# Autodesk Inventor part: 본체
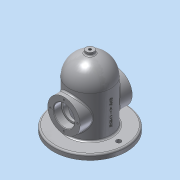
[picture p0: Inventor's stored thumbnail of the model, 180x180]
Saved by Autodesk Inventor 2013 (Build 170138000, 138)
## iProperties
Created: 2019-11
Part Number: 본체
Material: 알루미늄 6061
Document SubType Name: Modeling
Designer: Administrator
Density: 2.71 g/cm^3
Mass: 1111.16 g
Surface Area: 892.162 cm^2
Volume: 410.022 cm^3
Author: Administrator
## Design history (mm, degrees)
sketch "스케치1"
  geometry: C1 r 70 at (0, 0); 1 further point
  constraints: 1 centre point, 1 coincident
  dimensions: "d0" = 140 diameter of C1
extrude "돌출1" new body sketch "스케치1" distance "d1" = 10; taper "d2" = 0 deg
sketch "스케치2"
  geometry: C1 r 70 at (0, 0) reference; C2 r 40 at (0, 0)
  constraints: 1 centre point, 1 coincident
  dimensions: "d3" = 80 diameter of C2
extrude "돌출2" join sketch "스케치2" distance "d4" = 80; taper "d5" = 0 deg
sketch "스케치3"
  geometry: L1 (-70, 0)-(-70, 10) reference; L2 (-70, 10)-(-40, 10) reference; L3 (-40, 10)-(-40, 90) reference; L4 (-40, 90)-(40, 90) reference; L5 (40, 90)-(40, 10) reference; L6 (40, 10)-(70, 10) reference; L7 (70, 10)-(70, 0) reference; L8 (70, 0)-(-70, 0) reference; L9 (0, 130)-(0, 90); L10 (-40, 90)-(0, 90); A1 r 40 centre (0, 90) between (40, 90) and (0, 130); A2 r 40 centre (0, 90) between (0, 130) and (-40, 90); 1 further point
  constraints: 4 end point, 4 point on circle, 4 tangent, 2 centre point, 2 perpendicular
revolve "회전1" sketch "스케치3" stored, may be unused: angle "d6" = 90 deg
sketch "스케치4"
  geometry: L1 (-70, 0)-(-70, 10) reference; L2 (-70, 10)-(-40, 10) reference; L3 (-40, 10)-(-40, 90) reference; L4 (40, 90)-(40, 10) reference; L5 (40, 10)-(70, 10) reference; L6 (70, 10)-(70, 0) reference; L7 (70, 0)-(-70, 0) reference; C1 r 31 at (0, 50); A1 r 40 centre (0, 90) between (40, 90) and (0, 130) reference; A2 r 40 centre (0, 90) between (0, 130) and (-40, 90) reference; 1 further point
  constraints: 1 centre point, 1 vertical alignment
  dimensions: "d7" = 62 diameter of C1; "d8" = 50 distance from line of L7 C1.centre
extrude "돌출3" join sketch "스케치4" stored distance "d9" = 100; taper "d10" = 0 deg
sketch "스케치5"
  geometry: C1 r 70 at (0, 0) reference; C2 r 30 at (0, 0)
  constraints: 1 centre point, 1 coincident
  dimensions: "d11" = 60 diameter of C2
extrude "돌출4" cut sketch "스케치5" distance "d12" = 90; taper "d13" = 0 deg
sketch "스케치6"
  geometry: L1 (-70, 0)-(-70, 10) reference; L2 (-70, 10)-(-40, 10) reference; L3 (-40, 10)-(-40, 90) reference; L4 (40, 90)-(40, 10) reference; L5 (40, 10)-(70, 10) reference; L6 (70, 10)-(70, 0) reference; L7 (70, 0)-(30, 0) reference; L8 (30, 0)-(30, 90) reference; L9 (30, 90)-(-30, 90) reference; L10 (-30, 90)-(-30, 0) reference; L11 (-30, 0)-(-70, 0) reference; L12 (-30, 90)-(0, 90); L13 (0, 90)-(0, 120); A1 r 40 centre (0, 90) between (40, 90) and (0, 130) reference; A2 r 40 centre (0, 90) between (0, 130) and (-40, 90) reference; A3 r 30 centre (0, 90) between (30, 90) and (0, 120); A4 r 30 centre (0, 90) between (0, 120) and (-30, 90); 1 further point
  constraints: 4 end point, 4 point on circle, 4 tangent, 2 centre point, 1 collinear
revolve "회전2" sketch "스케치6" stored, may be unused: angle "d14" = 90 deg
sketch "스케치7"
  geometry: C1 r 31 at (0, 0) reference; C2 r 20 at (0, 0); 1 further point
  constraints: 1 centre point, 1 coincident
  dimensions: "d15" = 40 diameter of C2
extrude "돌출5" cut sketch "스케치7" distance "d16" = 15; taper "d17" = 0 deg
sketch "스케치8"
  geometry: C1 r 20 at (0, 0) reference; C2 r 16.5 at (0, 0); 1 further point
  constraints: 1 centre point, 1 coincident
  dimensions: "d18" = 33 diameter of C2
extrude "돌출6" cut sketch "스케치8" stored distance "d19" = 15; taper "d20" = 0 deg
sketch "스케치9"
  geometry: C1 r 31 at (0, 0) reference; C2 r 20 at (0, 0); 1 further point
  constraints: 1 centre point, 1 coincident
  dimensions: "d21" = 40 diameter of C2
extrude "돌출7" cut sketch "스케치9" distance "d22" = 15; taper "d23" = 0 deg
node "작업 평면1"
sketch "스케치10"
  geometry: C1 r 7.5 at (0, 0); 1 further point
  constraints: 1 centre point, 1 coincident
  dimensions: "d25" = 15 diameter of C1
extrude "돌출8" join sketch "스케치10" stored distance "d26" = 15; taper "d27" = 0 deg
fillet "모깎기1" dims "d28" = 0.3
chamfer "모따기1" distance "d29" = 1; stored, may be unused: second distance "d30" = 2, angle "d31" = 45 deg
sketch "스케치11"
  geometry: C1 r 7.5 at (0, 0) reference; 1 further point
  constraints: 1 coincident
hole "구멍1" sketch "스케치11" at (0, 0) diameter "d32" = 5.188; stored, may be unused: countersink angle "d36" = 90 deg, drill point angle "d38" = 118 deg; dims "d33" = 20, "d34" = 4, "d35" = 2, "d37" = 8
fillet "모깎기2" dims "d39" = 3
sketch "스케치12" dims "d40" = 52
  geometry: C1 r 31 at (0, 0) reference; C2 r 21 at (0, 0) reference; 3 further points
  constraints: 2 vertical alignment, 1 coincident, 2 other
hole "구멍2" sketch "스케치12" at (0, 26) diameter "d41" = 3.242; stored, may be unused: countersink angle "d45" = 90 deg, drill point angle "d47" = 118 deg; dims "d42" = 8, "d43" = 4, "d44" = 2, "d46" = 10
sketch "스케치13"
  geometry: C1 r 40 at (0, 0) reference; C2 r 70 at (0, 0) reference; A1 r 55 centre (0, 0) between (55, 0) and (-55, 0)
  constraints: 2 horizontal alignment, 2 point on circle, 1 centre point, 1 coincident
  dimensions: "d51" = 110 diameter of A1
hole "구멍3" sketch "스케치13" at (55, 0), (-55, 0) diameter "d52" = 9; stored, may be unused: countersink angle "d56" = 90 deg, drill point angle "d58" = 118 deg; dims "d53" = 8, "d54" = 4, "d55" = 2, "d57" = 10
node "작업 평면2"
sketch "스케치14"
  geometry: 2 further points
  constraints: 1 vertical alignment, 1 other
  dimensions: "d60" = 50 distance of point (0, 0) point (0, 50)
feature "엠보싱1" sketch "스케치14" dims "d61" = 0.5, "d62" = 0
fillet "모깎기3" dims "d63" = 3
node "솔리드1"
pattern_circular "원형 패턴1" dims angle "d49" = 360 deg
mirror "대칭1"
node "절단 모서리 투영1"
node "절단 모서리 투영2"
node "절단 모서리 투영3"
other parameters: "d24" = -135, "d59" = 93.25
